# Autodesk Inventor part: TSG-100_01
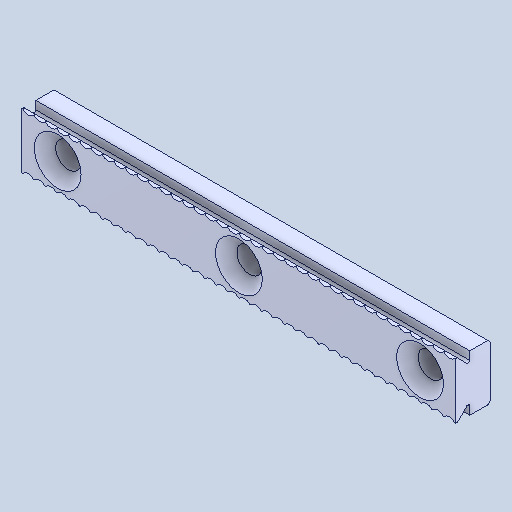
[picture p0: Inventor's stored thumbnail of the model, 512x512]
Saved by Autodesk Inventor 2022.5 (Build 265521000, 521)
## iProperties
Created: 2024-05
Part Number: TSG-100_01
Material: 一般
Document SubType Name: Modeling
Designer: ImaoCorp
Density: 1 g/cm^3
Appearance: 既定
Author: ImaoCorp
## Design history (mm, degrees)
feature "TSG-100_01"
node "ソリッド1"
